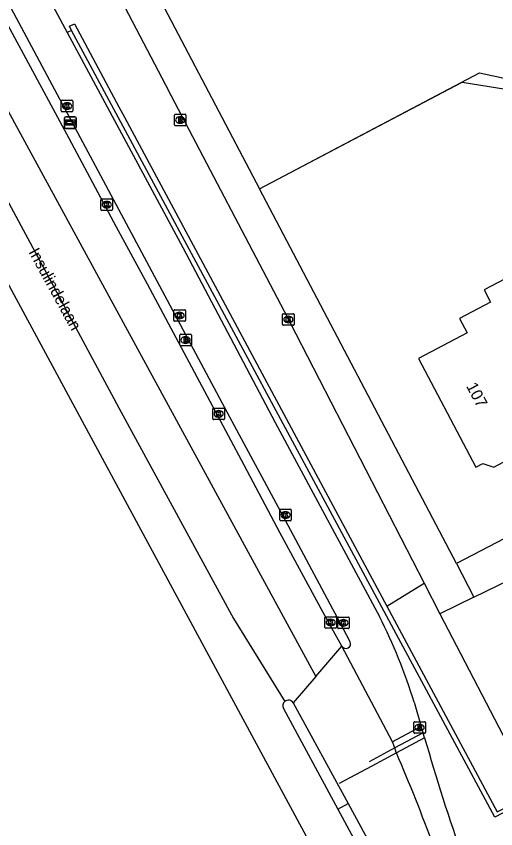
# Model space of a CAD drawing. Extents: x 162880 to 165536, y 384011 to 385179.
# Drawn here: x 162949.3 to 162990.9, y 384048 to 384118.4 of the extents above; entities that cross this region are included whole.
import ezdxf

# ---------------------------------------------------------------- set-up
doc = ezdxf.new("R2010")
doc.units = 0
for name, color, linetype in [('IMGEO_Berm_groen', 7, 'Continuous'), ('IMGEO_Fietspad_open', 7, 'Continuous'), ('IMGEO_Groenvoorziening', 7, 'Continuous'), ('IMGEO_Hek', 7, 'Continuous'), ('IMGEO_Kolk', 7, 'Continuous'), ('IMGEO_Lijnafwatering', 7, 'Continuous'), ('IMGEO_Muur', 7, 'Continuous'), ('IMGEO_Openbare_ruimte_label', 7, 'Continuous'), ('IMGEO_Pand', 7, 'Continuous'), ('IMGEO_Pand_nummerreeks', 7, 'Continuous'), ('IMGEO_Rijbaan_lokaal_gesloten', 7, 'Continuous'), ('IMGEO_Rijbaan_regionaal_gesloten', 7, 'Continuous'), ('IMGEO_Rioolput', 7, 'Continuous'), ('IMGEO_Verkeerseiland_open', 7, 'Continuous'), ('IMGEO_Voetpad_open', 7, 'Continuous'), ('IMGEO_Wegwijzer', 7, 'Continuous')]:
    doc.layers.add(name, color=color, linetype=linetype)

msp = doc.modelspace()

# ---------------------------------------------------------------- linework, layer by layer
at = {"layer": 'IMGEO_Berm_groen'}
msp.add_lwpolyline([(162981.431, 384067.333), (162984.67, 384069.309)], dxfattribs=at)
at = {"layer": 'IMGEO_Fietspad_open'}
for points in [[(162933.038, 384155.899), (162937.872, 384146.488), (162947.223, 384129.106), (162953.721, 384117.028)], [(162978.275, 384064.218), (162977.652, 384065.394), (162972.657, 384074.738), (162967.836, 384083.704), (162960.872, 384096.737), (162947.738, 384121.235), (162934.999, 384144.935), (162933.549, 384147.714), (162932.265, 384150.139), (162930.309, 384154.083)], [(162953.721, 384117.028), (162963.737, 384098.409), (162971.761, 384083.25), (162980.802, 384066.421)], [(162983.801, 384058.997), (162984.429, 384056.885)]]:
    msp.add_lwpolyline(points, dxfattribs=at)
for centre, radius, start, end in [((162940.769, 384045.931), 44.972, 16.8895, 27.10399), ((162977.898, 384064.068), 0.406, 210.63183, 21.73814)]:
    msp.add_arc(centre, radius, start, end, dxfattribs=at)
at = {"layer": 'IMGEO_Groenvoorziening'}
for points in [[(162970.391, 384103.478), (162989.485, 384113.534), (162997.371, 384111.834), (163004.613, 384098.171)], [(162986.032, 384066.664), (162992.592, 384054.068), (162995.929, 384055.751)]]:
    msp.add_lwpolyline(points, dxfattribs=at)
at = {"layer": 'IMGEO_Hek'}
msp.add_lwpolyline([(162970.391, 384103.478), (162987.968, 384112.735)], dxfattribs=at)
at = {"layer": 'IMGEO_Kolk'}
for p, q in [((162953.21, 384110.232), (162953.21, 384111.084)), ((162953.285, 384111.158), (162954.137, 384111.158)), ((162953.698, 384110.938), (162953.723, 384110.938)), ((162954.211, 384111.084), (162954.211, 384110.232)), ((162954.137, 384110.158), (162953.285, 384110.158)), ((162953.721, 384110.378), (162953.696, 384110.378)), ((162956.647, 384101.688), (162956.647, 384102.54)), ((162956.722, 384102.614), (162957.574, 384102.614)), ((162957.135, 384102.394), (162957.16, 384102.394)), ((162957.648, 384102.54), (162957.648, 384101.688)), ((162957.574, 384101.614), (162956.722, 384101.614)), ((162957.158, 384101.834), (162957.133, 384101.834)), ((162962.967, 384092.085), (162962.967, 384092.937)), ((162963.042, 384093.011), (162963.894, 384093.011)), ((162963.455, 384092.791), (162963.48, 384092.791)), ((162963.968, 384092.937), (162963.968, 384092.085)), ((162972.401, 384091.738), (162972.401, 384092.59)), ((162972.476, 384092.664), (162973.328, 384092.664)), ((162972.889, 384092.444), (162972.914, 384092.444)), ((162973.402, 384092.59), (162973.402, 384091.738)), ((162963.894, 384092.011), (162963.042, 384092.011)), ((162963.478, 384092.231), (162963.453, 384092.231)), ((162972.912, 384091.884), (162972.887, 384091.884)), ((162973.328, 384091.664), (162972.476, 384091.664)), ((162966.354, 384083.558), (162966.354, 384084.41)), ((162966.429, 384084.484), (162967.281, 384084.484)), ((162966.842, 384084.264), (162966.867, 384084.264)), ((162967.355, 384084.41), (162967.355, 384083.558)), ((162967.281, 384083.484), (162966.429, 384083.484)), ((162966.865, 384083.704), (162966.84, 384083.704)), ((162972.154, 384074.79), (162972.154, 384075.642)), ((162972.229, 384075.716), (162973.081, 384075.716)), ((162973.155, 384075.642), (162973.155, 384074.79)), ((162972.665, 384074.936), (162972.64, 384074.936)), ((162972.642, 384075.496), (162972.667, 384075.496)), ((162973.081, 384074.716), (162972.229, 384074.716)), ((162976.147, 384066.41), (162976.999, 384066.41)), ((162977.253, 384066.377), (162978.105, 384066.377)), ((162976.072, 384065.484), (162976.072, 384066.336)), ((162976.56, 384066.19), (162976.585, 384066.19)), ((162977.073, 384066.336), (162977.073, 384065.484)), ((162977.178, 384065.451), (162977.178, 384066.303)), ((162977.666, 384066.157), (162977.691, 384066.157)), ((162978.179, 384066.303), (162978.179, 384065.451)), ((162976.999, 384065.41), (162976.147, 384065.41)), ((162976.583, 384065.63), (162976.558, 384065.63)), ((162978.105, 384065.377), (162977.253, 384065.377)), ((162977.689, 384065.597), (162977.664, 384065.597))]:
    msp.add_line(p, q, dxfattribs=at)
for points in [[(162953.21, 384110.232), (162953.21, 384111.084)], [(162953.285, 384111.158), (162954.137, 384111.158)], [(162953.531, 384110.858), (162953.654, 384110.858), (162953.654, 384110.707), (162953.784, 384110.858), (162953.948, 384110.858), (162953.802, 384110.707), (162953.955, 384110.458), (162953.803, 384110.458), (162953.718, 384110.622), (162953.654, 384110.555), (162953.654, 384110.458), (162953.531, 384110.458), (162953.531, 384110.858)], [(162954.211, 384111.084), (162954.211, 384110.232)], [(162954.137, 384110.158), (162953.285, 384110.158)], [(162956.647, 384101.688), (162956.647, 384102.54)], [(162956.722, 384102.614), (162957.574, 384102.614)], [(162956.968, 384102.314), (162957.091, 384102.314), (162957.091, 384102.163), (162957.221, 384102.314), (162957.385, 384102.314), (162957.239, 384102.163), (162957.392, 384101.914), (162957.24, 384101.914), (162957.155, 384102.078), (162957.091, 384102.011), (162957.091, 384101.914), (162956.968, 384101.914), (162956.968, 384102.314)], [(162957.648, 384102.54), (162957.648, 384101.688)], [(162957.574, 384101.614), (162956.722, 384101.614)], [(162962.967, 384092.085), (162962.967, 384092.937)], [(162963.042, 384093.011), (162963.894, 384093.011)], [(162963.288, 384092.711), (162963.411, 384092.711), (162963.411, 384092.56), (162963.541, 384092.711), (162963.705, 384092.711), (162963.559, 384092.56), (162963.712, 384092.311), (162963.56, 384092.311), (162963.475, 384092.475), (162963.411, 384092.408), (162963.411, 384092.311), (162963.288, 384092.311), (162963.288, 384092.711)], [(162963.968, 384092.937), (162963.968, 384092.085)], [(162972.401, 384091.738), (162972.401, 384092.59)], [(162972.476, 384092.664), (162973.328, 384092.664)], [(162973.402, 384092.59), (162973.402, 384091.738)], [(162963.894, 384092.011), (162963.042, 384092.011)], [(162972.722, 384092.364), (162972.845, 384092.364), (162972.845, 384092.213), (162972.975, 384092.364), (162973.139, 384092.364), (162972.993, 384092.213), (162973.146, 384091.964), (162972.994, 384091.964), (162972.909, 384092.128), (162972.845, 384092.061), (162972.845, 384091.964), (162972.722, 384091.964), (162972.722, 384092.364)], [(162973.328, 384091.664), (162972.476, 384091.664)], [(162966.354, 384083.558), (162966.354, 384084.41)], [(162966.429, 384084.484), (162967.281, 384084.484)], [(162966.675, 384084.184), (162966.798, 384084.184), (162966.798, 384084.033), (162966.928, 384084.184), (162967.092, 384084.184), (162966.946, 384084.033), (162967.099, 384083.784), (162966.947, 384083.784), (162966.862, 384083.948), (162966.798, 384083.881), (162966.798, 384083.784), (162966.675, 384083.784), (162966.675, 384084.184)], [(162967.355, 384084.41), (162967.355, 384083.558)], [(162967.281, 384083.484), (162966.429, 384083.484)], [(162972.154, 384074.79), (162972.154, 384075.642)], [(162972.229, 384075.716), (162973.081, 384075.716)], [(162973.155, 384075.642), (162973.155, 384074.79)], [(162972.475, 384075.416), (162972.598, 384075.416), (162972.598, 384075.265), (162972.728, 384075.416), (162972.892, 384075.416), (162972.746, 384075.265), (162972.899, 384075.016), (162972.747, 384075.016), (162972.662, 384075.18), (162972.598, 384075.113), (162972.598, 384075.016), (162972.475, 384075.016), (162972.475, 384075.416)], [(162973.081, 384074.716), (162972.229, 384074.716)], [(162976.147, 384066.41), (162976.999, 384066.41)], [(162977.253, 384066.377), (162978.105, 384066.377)], [(162976.072, 384065.484), (162976.072, 384066.336)], [(162976.393, 384066.11), (162976.516, 384066.11), (162976.516, 384065.959), (162976.646, 384066.11), (162976.81, 384066.11), (162976.664, 384065.959), (162976.817, 384065.71), (162976.665, 384065.71), (162976.58, 384065.874), (162976.516, 384065.807), (162976.516, 384065.71), (162976.393, 384065.71), (162976.393, 384066.11)], [(162977.073, 384066.336), (162977.073, 384065.484)], [(162977.178, 384065.451), (162977.178, 384066.303)], [(162977.499, 384066.077), (162977.622, 384066.077), (162977.622, 384065.926), (162977.752, 384066.077), (162977.916, 384066.077), (162977.77, 384065.926), (162977.923, 384065.677), (162977.771, 384065.677), (162977.686, 384065.841), (162977.622, 384065.774), (162977.622, 384065.677), (162977.499, 384065.677), (162977.499, 384066.077)], [(162978.179, 384066.303), (162978.179, 384065.451)], [(162976.999, 384065.41), (162976.147, 384065.41)], [(162978.105, 384065.377), (162977.253, 384065.377)]]:
    msp.add_lwpolyline(points, dxfattribs=at)
for centre, start, end in [((162953.287, 384111.082), 91.55205, 178.44795), ((162953.287, 384111.082), 91.55205, 178.44795), ((162954.135, 384111.082), 1.55205, 88.44795), ((162954.135, 384111.082), 1.55205, 88.44795), ((162953.287, 384110.234), 181.55205, 268.44795), ((162953.287, 384110.234), 181.55205, 268.44795), ((162954.135, 384110.234), 271.55205, 358.44795), ((162954.135, 384110.234), 271.55205, 358.44795), ((162956.724, 384102.538), 91.55205, 178.44795), ((162956.724, 384102.538), 91.55205, 178.44795), ((162957.572, 384102.538), 1.55205, 88.44795), ((162957.572, 384102.538), 1.55205, 88.44795), ((162956.724, 384101.69), 181.55205, 268.44795), ((162956.724, 384101.69), 181.55205, 268.44795), ((162957.572, 384101.69), 271.55205, 358.44795), ((162957.572, 384101.69), 271.55205, 358.44795), ((162963.044, 384092.935), 91.55205, 178.44795), ((162963.044, 384092.935), 91.55205, 178.44795), ((162963.892, 384092.935), 1.55205, 88.44795), ((162963.892, 384092.935), 1.55205, 88.44795), ((162972.478, 384092.588), 91.55205, 178.44795), ((162972.478, 384092.588), 91.55205, 178.44795), ((162973.326, 384092.588), 1.55205, 88.44795), ((162973.326, 384092.588), 1.55205, 88.44795), ((162963.044, 384092.087), 181.55205, 268.44795), ((162963.044, 384092.087), 181.55205, 268.44795), ((162963.892, 384092.087), 271.55205, 358.44795), ((162963.892, 384092.087), 271.55205, 358.44795), ((162972.478, 384091.74), 181.55205, 268.44795), ((162972.478, 384091.74), 181.55205, 268.44795), ((162973.326, 384091.74), 271.55205, 358.44795), ((162973.326, 384091.74), 271.55205, 358.44795), ((162966.431, 384084.408), 91.55205, 178.44795), ((162966.431, 384084.408), 91.55205, 178.44795), ((162967.279, 384084.408), 1.55205, 88.44795), ((162967.279, 384084.408), 1.55205, 88.44795), ((162966.431, 384083.56), 181.55205, 268.44795), ((162966.431, 384083.56), 181.55205, 268.44795), ((162967.279, 384083.56), 271.55205, 358.44795), ((162967.279, 384083.56), 271.55205, 358.44795), ((162972.231, 384075.64), 91.55205, 178.44795), ((162972.231, 384075.64), 91.55205, 178.44795), ((162973.079, 384075.64), 1.55205, 88.44795), ((162973.079, 384075.64), 1.55205, 88.44795), ((162972.231, 384074.792), 181.55205, 268.44795), ((162972.231, 384074.792), 181.55205, 268.44795), ((162973.079, 384074.792), 271.55205, 358.44795), ((162973.079, 384074.792), 271.55205, 358.44795), ((162976.149, 384066.334), 91.55205, 178.44795), ((162976.149, 384066.334), 91.55205, 178.44795), ((162976.997, 384066.334), 1.55205, 88.44795), ((162976.997, 384066.334), 1.55205, 88.44795), ((162977.255, 384066.301), 91.55205, 178.44795), ((162977.255, 384066.301), 91.55205, 178.44795), ((162978.103, 384066.301), 1.55205, 88.44795), ((162978.103, 384066.301), 1.55205, 88.44795), ((162976.149, 384065.486), 181.55205, 268.44795), ((162976.149, 384065.486), 181.55205, 268.44795), ((162976.997, 384065.486), 271.55205, 358.44795), ((162976.997, 384065.486), 271.55205, 358.44795), ((162977.255, 384065.453), 181.55205, 268.44795), ((162977.255, 384065.453), 181.55205, 268.44795), ((162978.103, 384065.453), 271.55205, 358.44795), ((162978.103, 384065.453), 271.55205, 358.44795)]:
    msp.add_arc(centre, 0.0765, start, end, dxfattribs=at)
for centre, major_axis, ratio, start_param, end_param in [((162953.697, 384110.658), (-0.387, 0.002), 0.722429, 4.712389, 7.853982), ((162953.722, 384110.658), (-0.39, 0.002), 0.717154, 1.570796, 4.712389), ((162957.134, 384102.114), (-0.387, 0.002), 0.722429, 4.712389, 7.853982), ((162957.159, 384102.114), (-0.39, 0.002), 0.717154, 1.570796, 4.712389), ((162963.454, 384092.511), (-0.387, 0.002), 0.722429, 4.712389, 7.853982), ((162963.479, 384092.511), (-0.39, 0.002), 0.717154, 1.570796, 4.712389), ((162972.888, 384092.164), (-0.387, 0.002), 0.722429, 4.712389, 7.853982), ((162972.913, 384092.164), (-0.39, 0.002), 0.717154, 1.570796, 4.712389), ((162966.841, 384083.984), (-0.387, 0.002), 0.722429, 4.712389, 7.853982), ((162966.866, 384083.984), (-0.39, 0.002), 0.717154, 1.570796, 4.712389), ((162972.641, 384075.216), (-0.387, 0.002), 0.722429, 4.712389, 7.853982), ((162972.666, 384075.216), (-0.39, 0.002), 0.717154, 1.570796, 4.712389), ((162976.559, 384065.91), (-0.387, 0.002), 0.722429, 4.712389, 7.853982), ((162976.584, 384065.91), (-0.39, 0.002), 0.717154, 1.570796, 4.712389), ((162977.665, 384065.877), (-0.387, 0.002), 0.722429, 4.712389, 7.853982), ((162977.69, 384065.877), (-0.39, 0.002), 0.717154, 1.570796, 4.712389)]:
    msp.add_ellipse(centre, major_axis=major_axis, ratio=ratio, start_param=start_param, end_param=end_param, dxfattribs=at)
at = {"layer": 'IMGEO_Lijnafwatering'}
for points in [[(162984.721, 384055.91), (162982.273, 384054.6), (162980.133, 384053.455), (162977.305, 384051.942)], [(162984.582, 384056.358), (162982.121, 384055.034), (162979.913, 384053.846)]]:
    msp.add_lwpolyline(points, dxfattribs=at)
at = {"layer": 'IMGEO_Muur'}
for points in [[(162954.108, 384117.22), (162953.92, 384117.569), (162954.341, 384117.797), (162958.202, 384110.605), (162958.691, 384109.694), (162981.431, 384067.333)], [(162991.582, 384049.441), (162990.798, 384049.049), (162954.108, 384117.22)], [(162987.968, 384112.735), (162997.727, 384111.162), (163004.613, 384098.171)], [(162981.431, 384067.333), (162991.01, 384049.488), (163000.563, 384054.317)]]:
    msp.add_lwpolyline(points, dxfattribs=at)
at = {"layer": 'IMGEO_Pand'}
msp.add_lwpolyline([(162989.161, 384079.36), (162989.763, 384079.677), (162990.721, 384079.381), (162992.728, 384080.44), (162993.008, 384081.346), (163000, 384085.013), (163000.295, 384085.166), (163000, 384085.727), (162994.993, 384095.242), (162994.409, 384094.934), (162993.513, 384096.632), (162989.891, 384094.72), (162990.441, 384093.678), (162987.755, 384092.26), (162988.409, 384091.022), (162984.182, 384088.791), (162989.161, 384079.36)], dxfattribs=at)
at = {"layer": 'IMGEO_Rijbaan_lokaal_gesloten'}
for points in [[(162981.934, 384055.564), (162977.549, 384063.861)], [(162973.315, 384058.937), (162978.076, 384050.216)], [(162984.429, 384056.885), (162981.934, 384055.564)], [(162984.721, 384055.91), (162984.582, 384056.358), (162984.429, 384056.885)], [(162982.273, 384054.6), (162982.263, 384054.629), (162982.121, 384055.034), (162981.934, 384055.564)], [(162978.076, 384050.216), (162984.172, 384039.047), (162995.17, 384018.593)]]:
    msp.add_lwpolyline(points, dxfattribs=at)
for centre, radius, start, end in [((163173.037, 384110.079), 195.951, 196.04776, 199.24386), ((162836.273, 383991.591), 159.016, 20.19842, 23.34345)]:
    msp.add_arc(centre, radius, start, end, dxfattribs=at)
at = {"layer": 'IMGEO_Rijbaan_regionaal_gesloten'}
for points in [[(162925.808, 384218.268), (162924.406, 384214.339), (162923.042, 384210.566), (162921.831, 384206.759), (162921.005, 384203.8), (162920.142, 384199.922), (162919.5, 384195.956), (162919.067, 384191.957), (162918.781, 384187.947), (162918.728, 384184.033), (162918.834, 384180.023), (162919.29, 384176.002), (162919.842, 384172.079), (162920.544, 384168.175), (162921.527, 384164.257), (162922.622, 384160.668), (162923.876, 384157.224), (162925.32, 384153.606), (162927.054, 384149.995), (162941.468, 384123.295), (162975.292, 384061.236)], [(162989.779, 384019.039), (162985.285, 384027.338), (162969.546, 384056.451), (162934.139, 384122.004), (162927.269, 384134.699), (162919.627, 384148.98), (162917.856, 384152.526), (162916.199, 384156.183), (162915.086, 384158.94), (162914.148, 384161.675), (162913.523, 384163.62), (162912.54, 384167.345), (162911.658, 384171.418), (162910.97, 384175.312), (162910.653, 384178.24), (162910.532, 384181.105), (162910.375, 384184.971), (162910.273, 384188.816), (162910.227, 384197.762), (162910.167, 384200.723)], [(162916.031, 384170.737), (162917.1, 384164.017), (162917.376, 384162.869), (162919.483, 384157.241), (162921.12, 384153.691), (162923.818, 384148.334), (162938.264, 384121.566), (162958.401, 384084.137), (162968.149, 384066.24), (162972.6, 384059.067)], [(162977.549, 384063.861), (162975.924, 384066.775), (162972.201, 384073.655), (162969.056, 384079.527), (162966.347, 384084.631), (162960.687, 384095.222), (162957.998, 384100.168), (162953.892, 384107.862), (162947.989, 384118.779), (162942.396, 384129.219), (162936.921, 384139.438), (162933.346, 384146.147), (162929.808, 384152.971), (162929.465, 384153.664)], [(162975.292, 384061.236), (162977.549, 384063.861)], [(162975.292, 384061.236), (162973.315, 384058.937)], [(162972.482, 384058.455), (162977.19, 384049.734)], [(162977.19, 384049.734), (162993.944, 384018.694)]]:
    msp.add_lwpolyline(points, dxfattribs=at)
for centre, radius, start, end in [((162972.899, 384058.692), 0.48, 128.58391, 209.58949), ((162972.901, 384058.691), 0.481, 30.68085, 128.70945)]:
    msp.add_arc(centre, radius, start, end, dxfattribs=at)
at = {"layer": 'IMGEO_Rioolput'}
for p, q in [((162963.022, 384109.028), (162963.022, 384109.88)), ((162963.097, 384109.954), (162963.949, 384109.954)), ((162963.51, 384109.734), (162963.535, 384109.734)), ((162964.023, 384109.88), (162964.023, 384109.028)), ((162963.949, 384108.954), (162963.097, 384108.954)), ((162963.533, 384109.174), (162963.508, 384109.174)), ((162963.487, 384089.954), (162963.487, 384090.806)), ((162963.562, 384090.88), (162964.414, 384090.88)), ((162963.975, 384090.66), (162964, 384090.66)), ((162964.488, 384090.806), (162964.488, 384089.954)), ((162964.414, 384089.88), (162963.562, 384089.88)), ((162963.998, 384090.1), (162963.973, 384090.1)), ((162983.781, 384056.381), (162983.781, 384057.233)), ((162983.856, 384057.307), (162984.708, 384057.307)), ((162984.782, 384057.233), (162984.782, 384056.381)), ((162984.292, 384056.527), (162984.267, 384056.527)), ((162984.269, 384057.087), (162984.294, 384057.087)), ((162984.708, 384056.307), (162983.856, 384056.307))]:
    msp.add_line(p, q, dxfattribs=at)
for points in [[(162963.022, 384109.028), (162963.022, 384109.88)], [(162963.097, 384109.954), (162963.949, 384109.954)], [(162963.611, 384109.652), (162963.359, 384109.654), (162963.359, 384109.254)], [(162963.359, 384109.254), (162963.483, 384109.254), (162963.483, 384109.416), (162963.494, 384109.416)], [(162963.537, 384109.573), (162963.483, 384109.573), (162963.483, 384109.492)], [(162963.483, 384109.492), (162963.535, 384109.492)], [(162963.541, 384109.387), (162963.612, 384109.254), (162963.752, 384109.254), (162963.687, 384109.38)], [(162964.023, 384109.88), (162964.023, 384109.028)], [(162963.949, 384108.954), (162963.097, 384108.954)], [(162963.487, 384089.954), (162963.487, 384090.806)], [(162963.562, 384090.88), (162964.414, 384090.88)], [(162964.076, 384090.578), (162963.824, 384090.58), (162963.824, 384090.18)], [(162963.824, 384090.18), (162963.948, 384090.18), (162963.948, 384090.342), (162963.959, 384090.342)], [(162964.002, 384090.499), (162963.948, 384090.499), (162963.948, 384090.418)], [(162963.948, 384090.418), (162964, 384090.418)], [(162964.006, 384090.313), (162964.077, 384090.18), (162964.217, 384090.18), (162964.152, 384090.306)], [(162964.488, 384090.806), (162964.488, 384089.954)], [(162964.414, 384089.88), (162963.562, 384089.88)], [(162983.781, 384056.381), (162983.781, 384057.233)], [(162983.856, 384057.307), (162984.708, 384057.307)], [(162984.782, 384057.233), (162984.782, 384056.381)], [(162984.37, 384057.005), (162984.118, 384057.007), (162984.118, 384056.607)], [(162984.118, 384056.607), (162984.242, 384056.607), (162984.242, 384056.769), (162984.253, 384056.769)], [(162984.296, 384056.926), (162984.242, 384056.926), (162984.242, 384056.845)], [(162984.242, 384056.845), (162984.294, 384056.845)], [(162984.3, 384056.74), (162984.371, 384056.607), (162984.511, 384056.607), (162984.446, 384056.733)], [(162984.708, 384056.307), (162983.856, 384056.307)]]:
    msp.add_lwpolyline(points, dxfattribs=at)
for centre, radius, start, end in [((162963.099, 384109.878), 0.0765, 91.55205, 178.44795), ((162963.099, 384109.878), 0.0765, 91.55205, 178.44795), ((162963.493, 384109.363), 0.0533, 26.02933, 88.69889), ((162963.519, 384109.681), 0.19, 274.7715, 282.96867), ((162963.543, 384109.477), 0.0964, 77.00612, 93.18647), ((162963.557, 384109.534), 0.0378, 276.66336, 79.67722), ((162963.61, 384109.542), 0.109, 350.36119, 89.41601), ((162963.608, 384109.542), 0.112, 277.58423, 350.98172), ((162963.592, 384109.327), 0.108, 29.51342, 73.79051), ((162963.947, 384109.878), 0.0765, 1.55205, 88.44795), ((162963.947, 384109.878), 0.0765, 1.55205, 88.44795), ((162963.099, 384109.03), 0.0765, 181.55205, 268.44795), ((162963.099, 384109.03), 0.0765, 181.55205, 268.44795), ((162963.947, 384109.03), 0.0765, 271.55205, 358.44795), ((162963.947, 384109.03), 0.0765, 271.55205, 358.44795), ((162963.564, 384090.804), 0.0765, 91.55205, 178.44795), ((162963.564, 384090.804), 0.0765, 91.55205, 178.44795), ((162963.958, 384090.289), 0.0533, 26.02933, 88.69889), ((162963.984, 384090.607), 0.19, 274.7715, 282.96867), ((162964.008, 384090.403), 0.0964, 77.00612, 93.18647), ((162964.022, 384090.46), 0.0378, 276.66336, 79.67722), ((162964.075, 384090.468), 0.109, 350.36119, 89.41601), ((162964.073, 384090.468), 0.112, 277.58423, 350.98172), ((162964.057, 384090.253), 0.108, 29.51342, 73.79051), ((162964.412, 384090.804), 0.0765, 1.55205, 88.44795), ((162964.412, 384090.804), 0.0765, 1.55205, 88.44795), ((162963.564, 384089.956), 0.0765, 181.55205, 268.44795), ((162963.564, 384089.956), 0.0765, 181.55205, 268.44795), ((162964.412, 384089.956), 0.0765, 271.55205, 358.44795), ((162964.412, 384089.956), 0.0765, 271.55205, 358.44795), ((162983.858, 384057.231), 0.0765, 91.55205, 178.44795), ((162983.858, 384057.231), 0.0765, 91.55205, 178.44795), ((162984.706, 384057.231), 0.0765, 1.55205, 88.44795), ((162984.706, 384057.231), 0.0765, 1.55205, 88.44795), ((162984.252, 384056.716), 0.0533, 26.02933, 88.69889), ((162984.278, 384057.034), 0.19, 274.7715, 282.96867), ((162984.302, 384056.83), 0.0964, 77.00612, 93.18647), ((162984.316, 384056.887), 0.0378, 276.66336, 79.67722), ((162984.369, 384056.895), 0.109, 350.36119, 89.41601), ((162984.367, 384056.895), 0.112, 277.58423, 350.98172), ((162984.351, 384056.68), 0.108, 29.51342, 73.79051), ((162983.858, 384056.383), 0.0765, 181.55205, 268.44795), ((162983.858, 384056.383), 0.0765, 181.55205, 268.44795), ((162984.706, 384056.383), 0.0765, 271.55205, 358.44795), ((162984.706, 384056.383), 0.0765, 271.55205, 358.44795)]:
    msp.add_arc(centre, radius, start, end, dxfattribs=at)
for centre, major_axis, ratio, start_param, end_param in [((162963.509, 384109.454), (-0.387, 0.002), 0.722429, 4.712389, 7.853982), ((162963.534, 384109.454), (-0.39, 0.002), 0.717154, 1.570796, 4.712389), ((162963.974, 384090.38), (-0.387, 0.002), 0.722429, 4.712389, 7.853982), ((162963.999, 384090.38), (-0.39, 0.002), 0.717154, 1.570796, 4.712389), ((162984.268, 384056.807), (-0.387, 0.002), 0.722429, 4.712389, 7.853982), ((162984.293, 384056.807), (-0.39, 0.002), 0.717154, 1.570796, 4.712389)]:
    msp.add_ellipse(centre, major_axis=major_axis, ratio=ratio, start_param=start_param, end_param=end_param, dxfattribs=at)
at = {"layer": 'IMGEO_Verkeerseiland_open'}
msp.add_lwpolyline([(162977.19, 384049.734), (162978.076, 384050.216)], dxfattribs=at)
at = {"layer": 'IMGEO_Voetpad_open'}
for points in [[(162930.3, 384162.837), (162934.711, 384164.997), (162962.245, 384112.496), (162962.739, 384111.555), (162972.528, 384092.889), (162984.67, 384069.309)], [(162942.595, 384156.45), (162942.963, 384155.663), (162942.983, 384155.624), (162950.386, 384141.542), (162950.906, 384141.816), (162954.621, 384134.748), (162954.097, 384134.472), (162962.154, 384119.148), (162970.391, 384103.478)], [(162954.108, 384117.22), (162953.721, 384117.028)], [(162987.483, 384071.025), (162970.391, 384103.478)], [(163012.207, 384083.845), (163000, 384077.515), (162995.091, 384074.97), (162987.483, 384071.025)], [(162987.483, 384071.025), (162988.989, 384068.099)], [(162988.989, 384068.099), (162994.089, 384070.573)], [(162984.67, 384069.309), (162986.032, 384066.664)], [(162988.989, 384068.099), (162986.032, 384066.664)]]:
    msp.add_lwpolyline(points, dxfattribs=at)
at = {"layer": 'IMGEO_Wegwijzer'}
for p, q in [((162953.499, 384108.828), (162953.499, 384109.628)), ((162953.499, 384109.628), (162953.499, 384108.828)), ((162953.599, 384109.728), (162954.389, 384109.728)), ((162954.389, 384109.728), (162953.599, 384109.728)), ((162954.489, 384109.628), (162954.489, 384108.828)), ((162954.489, 384108.828), (162954.489, 384109.628)), ((162954.389, 384108.728), (162953.599, 384108.728)), ((162953.599, 384108.728), (162954.389, 384108.728))]:
    msp.add_line(p, q, dxfattribs=at)
for points in [[(162953.6, 384109.46), (162954.388, 384109.46), (162954.388, 384108.996), (162953.6, 384108.996), (162953.6, 384109.46)], [(162953.665, 384109.312), (162953.665, 384109.228), (162953.665, 384109.144), (162954.076, 384109.144), (162954.076, 384109.061), (162954.323, 384109.228), (162954.076, 384109.395), (162954.076, 384109.312), (162953.665, 384109.312)]]:
    msp.add_lwpolyline(points, dxfattribs=at)
for centre, start, end in [((162953.599, 384109.628), 90, 180), ((162953.599, 384109.628), 90, 180), ((162954.389, 384109.628), 0, 90), ((162954.389, 384109.628), 360, 90), ((162953.599, 384108.828), 180, 270), ((162953.599, 384108.828), 180, 270), ((162954.389, 384108.828), 270, 0), ((162954.389, 384108.828), 270, 0)]:
    msp.add_arc(centre, 0.1, start, end, dxfattribs=at)

# ---------------------------------------------------------------- texts
at = {"layer": 'IMGEO_Openbare_ruimte_label'}
msp.add_text('Insulindelaan', height=1, rotation=298.74304, dxfattribs=at).set_placement((162950.341, 384098.019))
at = {"layer": 'IMGEO_Pand_nummerreeks'}
msp.add_text('107', height=1, rotation=297.83136, dxfattribs=at).set_placement((162988.299, 384086.39))

doc.saveas('drawing.dxf')
